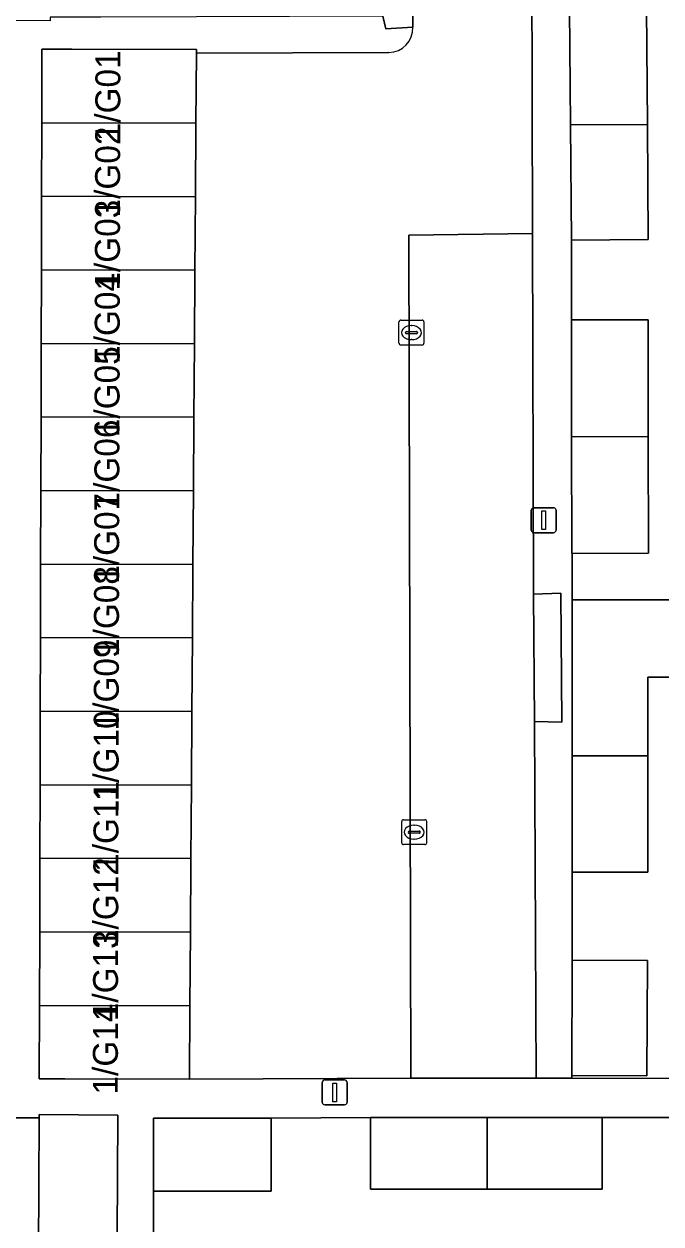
# Model space of a CAD drawing. Extents: x 160732 to 162107, y 387428 to 388479.
# Drawn here: x 161107.54 to 161133.07, y 387874.51 to 387922.63 of the extents above; entities that cross this region are included whole.
import ezdxf

# ---------------------------------------------------------------- set-up
doc = ezdxf.new("R2010")
doc.units = 0
for name, color, linetype in [('IMGEO_Erf', 7, 'Continuous'), ('IMGEO_Kolk', 7, 'Continuous'), ('IMGEO_Lichtmast', 7, 'Continuous'), ('IMGEO_Pand', 7, 'Continuous'), ('IMGEO_Pand_nummerreeks', 7, 'Continuous'), ('IMGEO_Parkeervlak_open', 7, 'Continuous'), ('IMGEO_Rijbaan_lokaal_open', 7, 'Continuous'), ('IMGEO_Voetpad_open', 7, 'Continuous')]:
    doc.layers.add(name, color=color, linetype=linetype)

msp = doc.modelspace()

# ---------------------------------------------------------------- linework, layer by layer
at = {"layer": 'IMGEO_Erf'}
for points in [[(161132.486, 387923.268), (161132.524, 387918.598), (161132.562, 387913.986), (161129.479, 387913.961), (161129.479, 387910.767), (161132.553, 387910.772), (161132.562, 387906.088), (161132.57, 387901.405), (161129.516, 387901.399), (161129.514, 387899.541), (161132.548, 387899.539), (161134.822, 387899.538)], [(161134.819, 387896.433), (161132.544, 387896.435), (161132.541, 387893.282), (161132.537, 387888.623), (161129.504, 387888.625), (161129.516, 387885.088), (161132.524, 387885.072), (161132.5, 387880.449), (161129.492, 387880.464), (161129.492, 387880.352), (161139.706, 387880.338)], [(161154.158, 387875.498), (161154.167, 387878.879), (161152.564, 387878.883), (161152.576, 387875.174), (161145.855, 387875.151), (161145.843, 387878.86), (161143.979, 387878.784), (161143.981, 387875.913), (161139.376, 387875.912), (161134.698, 387875.91), (161134.696, 387878.78), (161130.708, 387878.778), (161130.71, 387875.907), (161126.108, 387875.906), (161121.427, 387875.904), (161121.425, 387878.774), (161117.443, 387878.756), (161117.445, 387875.822), (161112.733, 387875.821), (161112.735, 387867.648)], [(161108.123, 387873.424), (161108.152, 387878.764), (161106.96, 387878.771)]]:
    msp.add_lwpolyline(points, dxfattribs=at)
at = {"layer": 'IMGEO_Kolk'}
for p, q in [((161122.57, 387909.83), (161122.57, 387910.682)), ((161122.645, 387910.756), (161123.497, 387910.756)), ((161123.571, 387910.682), (161123.571, 387909.83)), ((161122.829, 387910.25), (161122.829, 387910.262)), ((161123.267, 387910.213), (161122.869, 387910.213)), ((161122.872, 387910.299), (161123.27, 387910.299)), ((161123.058, 387910.536), (161123.083, 387910.536)), ((161123.313, 387910.262), (161123.313, 387910.25)), ((161123.497, 387909.756), (161122.645, 387909.756)), ((161123.081, 387909.976), (161123.056, 387909.976)), ((161122.678, 387889.796), (161122.678, 387890.648)), ((161122.753, 387890.722), (161123.605, 387890.722)), ((161123.166, 387890.502), (161123.191, 387890.502)), ((161123.679, 387890.648), (161123.679, 387889.796)), ((161122.937, 387890.216), (161122.937, 387890.228)), ((161123.375, 387890.179), (161122.977, 387890.179)), ((161122.98, 387890.265), (161123.378, 387890.265)), ((161123.189, 387889.942), (161123.164, 387889.942)), ((161123.421, 387890.228), (161123.421, 387890.216)), ((161123.605, 387889.722), (161122.753, 387889.722))]:
    msp.add_line(p, q, dxfattribs=at)
for points in [[(161122.57, 387909.83), (161122.57, 387910.682)], [(161122.645, 387910.756), (161123.497, 387910.756)], [(161123.571, 387910.682), (161123.571, 387909.83)], [(161123.497, 387909.756), (161122.645, 387909.756)], [(161122.678, 387889.796), (161122.678, 387890.648)], [(161122.753, 387890.722), (161123.605, 387890.722)], [(161123.679, 387890.648), (161123.679, 387889.796)], [(161123.605, 387889.722), (161122.753, 387889.722)]]:
    msp.add_lwpolyline(points, dxfattribs=at)
for centre, radius, start, end in [((161122.647, 387910.68), 0.0765, 91.552, 178.448), ((161122.647, 387910.68), 0.0765, 91.552, 178.448), ((161123.495, 387910.68), 0.0765, 1.552, 88.448), ((161123.495, 387910.68), 0.0765, 1.552, 88.448), ((161122.869, 387910.259), 0.0403, 85.8775, 175.7526), ((161122.866, 387910.249), 0.0366, 178.938, 274.7102), ((161123.27, 387910.256), 0.043, 264.8664, 352.4533), ((161123.274, 387910.261), 0.0386, 1.7309, 96.639), ((161122.647, 387909.832), 0.0765, 181.552, 268.448), ((161122.647, 387909.832), 0.0765, 181.552, 268.448), ((161123.495, 387909.832), 0.0765, 271.552, 358.448), ((161123.495, 387909.832), 0.0765, 271.552, 358.448), ((161122.755, 387890.646), 0.0765, 91.552, 178.448), ((161122.755, 387890.646), 0.0765, 91.552, 178.448), ((161123.603, 387890.646), 0.0765, 1.552, 88.448), ((161123.603, 387890.646), 0.0765, 1.552, 88.448), ((161122.977, 387890.225), 0.0403, 85.8775, 175.7526), ((161122.974, 387890.215), 0.0366, 178.938, 274.7102), ((161123.378, 387890.222), 0.043, 264.8664, 352.4533), ((161123.382, 387890.227), 0.0386, 1.7309, 96.639), ((161122.755, 387889.798), 0.0765, 181.552, 268.448), ((161122.755, 387889.798), 0.0765, 181.552, 268.448), ((161123.603, 387889.798), 0.0765, 271.552, 358.448), ((161123.603, 387889.798), 0.0765, 271.552, 358.448)]:
    msp.add_arc(centre, radius, start, end, dxfattribs=at)
for centre, major_axis, ratio, start_param, end_param in [((161123.057, 387910.256), (-0.387, 0.002), 0.722429, 4.712389, 7.853982), ((161123.082, 387910.256), (-0.39, 0.002), 0.717154, 1.570796, 4.712389), ((161123.165, 387890.222), (-0.387, 0.002), 0.722429, 4.712389, 7.853982), ((161123.19, 387890.222), (-0.39, 0.002), 0.717154, 1.570796, 4.712389)]:
    msp.add_ellipse(centre, major_axis=major_axis, ratio=ratio, start_param=start_param, end_param=end_param, dxfattribs=at)
at = {"layer": 'IMGEO_Lichtmast'}
for p, q in [((161127.873, 387902.331), (161127.873, 387903.131)), ((161127.873, 387903.131), (161127.873, 387902.331)), ((161127.973, 387903.231), (161128.763, 387903.231)), ((161128.763, 387903.231), (161127.973, 387903.231)), ((161128.863, 387903.131), (161128.863, 387902.331)), ((161128.863, 387902.331), (161128.863, 387903.131)), ((161128.763, 387902.231), (161127.973, 387902.231)), ((161127.973, 387902.231), (161128.763, 387902.231)), ((161119.597, 387880.287), (161120.387, 387880.287)), ((161120.387, 387880.287), (161119.597, 387880.287)), ((161119.497, 387879.387), (161119.497, 387880.187)), ((161119.497, 387880.187), (161119.497, 387879.387)), ((161120.487, 387880.187), (161120.487, 387879.387)), ((161120.487, 387879.387), (161120.487, 387880.187)), ((161120.387, 387879.287), (161119.597, 387879.287)), ((161119.597, 387879.287), (161120.387, 387879.287))]:
    msp.add_line(p, q, dxfattribs=at)
for points in [[(161128.293, 387903.106), (161128.443, 387903.106), (161128.443, 387902.356), (161128.293, 387902.356), (161128.293, 387903.106)], [(161119.917, 387880.162), (161120.067, 387880.162), (161120.067, 387879.412), (161119.917, 387879.412), (161119.917, 387880.162)]]:
    msp.add_lwpolyline(points, dxfattribs=at)
for centre, start, end in [((161127.973, 387903.131), 90, 180), ((161127.973, 387903.131), 90, 180), ((161128.763, 387903.131), 0, 90), ((161128.763, 387903.131), 360, 90), ((161127.973, 387902.331), 180, 270), ((161127.973, 387902.331), 180, 270), ((161128.763, 387902.331), 270, 0), ((161128.763, 387902.331), 270, 0), ((161119.597, 387880.187), 90, 180), ((161119.597, 387880.187), 90, 180), ((161120.387, 387880.187), 0, 90), ((161120.387, 387880.187), 360, 90), ((161119.597, 387879.387), 180, 270), ((161119.597, 387879.387), 180, 270), ((161120.387, 387879.387), 270, 0), ((161120.387, 387879.387), 270, 0)]:
    msp.add_arc(centre, 0.1, start, end, dxfattribs=at)
at = {"layer": 'IMGEO_Pand'}
for points in [[(161132.524, 387918.598), (161132.486, 387923.268), (161129.402, 387923.242), (161129.441, 387918.592)], [(161114.453, 387921.466), (161114.454, 387921.609), (161109.455, 387921.622), (161108.261, 387921.624), (161108.253, 387918.674), (161114.434, 387918.658)], [(161114.434, 387918.658), (161108.253, 387918.674), (161108.246, 387915.724), (161114.413, 387915.708)], [(161129.441, 387918.592), (161129.479, 387913.961), (161132.562, 387913.986), (161132.524, 387918.598)], [(161114.413, 387915.708), (161108.246, 387915.724), (161108.238, 387912.775), (161114.393, 387912.759)], [(161114.393, 387912.759), (161108.238, 387912.775), (161108.23, 387909.825), (161114.373, 387909.809)], [(161132.562, 387906.088), (161132.553, 387910.772), (161129.479, 387910.767), (161129.488, 387906.082)], [(161114.373, 387909.809), (161108.23, 387909.825), (161108.223, 387906.875), (161114.353, 387906.859)], [(161114.353, 387906.859), (161108.223, 387906.875), (161108.215, 387903.925), (161114.332, 387903.909)], [(161132.562, 387906.088), (161129.488, 387906.082), (161129.497, 387901.399), (161129.516, 387901.399), (161132.57, 387901.405)], [(161114.332, 387903.909), (161108.215, 387903.925), (161108.208, 387900.976), (161114.312, 387900.96)], [(161114.312, 387900.96), (161108.208, 387900.976), (161108.2, 387898.026), (161114.292, 387898.01)], [(161129.514, 387899.541), (161129.513, 387897.943), (161129.509, 387893.285), (161132.541, 387893.282), (161132.544, 387896.435), (161134.819, 387896.433), (161134.822, 387899.538), (161132.548, 387899.539)], [(161114.292, 387898.01), (161108.2, 387898.026), (161108.192, 387895.076), (161114.271, 387895.06)], [(161114.271, 387895.06), (161108.192, 387895.076), (161108.185, 387892.126), (161114.251, 387892.11)], [(161129.509, 387893.285), (161129.504, 387888.625), (161132.537, 387888.623), (161132.541, 387893.282)], [(161114.251, 387892.11), (161108.185, 387892.126), (161108.177, 387889.176), (161114.231, 387889.161)], [(161114.231, 387889.161), (161108.177, 387889.176), (161108.169, 387886.227), (161114.211, 387886.211)], [(161114.211, 387886.211), (161108.169, 387886.227), (161108.162, 387883.277), (161114.19, 387883.261)], [(161132.5, 387880.449), (161132.524, 387885.072), (161129.516, 387885.088), (161129.492, 387880.464)], [(161114.19, 387883.261), (161108.162, 387883.277), (161108.154, 387880.327), (161109.171, 387880.324), (161114.17, 387880.311)], [(161111.301, 387878.877), (161108.153, 387878.895), (161108.152, 387878.764), (161108.123, 387873.424), (161108.189, 387873.439), (161108.189, 387874.053), (161111.274, 387874.053)], [(161117.445, 387875.822), (161117.443, 387878.756), (161112.731, 387878.755), (161112.733, 387875.821)], [(161126.107, 387878.776), (161121.425, 387878.774), (161121.427, 387875.904), (161126.108, 387875.906)], [(161126.108, 387875.906), (161130.71, 387875.907), (161130.708, 387878.778), (161126.107, 387878.776)]]:
    msp.add_lwpolyline(points, close=True, dxfattribs=at)
at = {"layer": 'IMGEO_Parkeervlak_open'}
msp.add_lwpolyline([(161127.963, 387899.767), (161127.926, 387914.225), (161122.958, 387914.162), (161123.049, 387880.357), (161128.071, 387880.354), (161128.007, 387894.664)], close=True, dxfattribs=at)
at = {"layer": 'IMGEO_Rijbaan_lokaal_open'}
for points in [[(161122.958, 387914.162), (161127.926, 387914.225), (161127.885, 387930.449), (161127.846, 387935.311), (161127.866, 387945.068), (161123.097, 387945.063), (161123.102, 387943.562), (161123.156, 387927.578), (161123.128, 387922.5)], [(161122.168, 387921.485), (161114.453, 387921.466), (161114.434, 387918.658), (161114.413, 387915.708), (161114.393, 387912.759), (161114.373, 387909.809), (161114.353, 387906.859), (161114.332, 387903.909), (161114.312, 387900.96), (161114.292, 387898.01), (161114.271, 387895.06), (161114.251, 387892.11), (161114.231, 387889.161), (161114.211, 387886.211), (161114.19, 387883.261), (161114.17, 387880.311), (161123.049, 387880.357), (161122.958, 387914.162)]]:
    msp.add_lwpolyline(points, dxfattribs=at)
msp.add_arc((161122.14, 387922.473), 0.989, 271.6458, 1.5446, dxfattribs=at)
at = {"layer": 'IMGEO_Voetpad_open'}
for points in [[(161127.885, 387930.449), (161127.926, 387914.225), (161127.963, 387899.767), (161129.059, 387899.811), (161129.101, 387894.639), (161128.007, 387894.664), (161128.071, 387880.354), (161129.492, 387880.352), (161129.492, 387880.464), (161129.516, 387885.088), (161129.504, 387888.625), (161129.509, 387893.285), (161129.513, 387897.943), (161129.514, 387899.541), (161129.516, 387901.399), (161129.497, 387901.399), (161129.488, 387906.082), (161129.479, 387910.767), (161129.479, 387913.961), (161129.441, 387918.592), (161129.402, 387923.242)], [(161123.128, 387922.5), (161122.048, 387922.435), (161121.928, 387922.943), (161114.448, 387922.918), (161110.618, 387922.905), (161108.586, 387922.912), (161108.585, 387922.765), (161102.19, 387922.788)], [(161139.706, 387880.338), (161129.492, 387880.352), (161128.071, 387880.354), (161123.049, 387880.357), (161114.17, 387880.311), (161109.171, 387880.324), (161108.154, 387880.327), (161108.162, 387883.277), (161108.169, 387886.227), (161108.177, 387889.176), (161108.185, 387892.126), (161108.192, 387895.076), (161108.2, 387898.026), (161108.208, 387900.976), (161108.215, 387903.925), (161108.223, 387906.875), (161108.23, 387909.825), (161108.238, 387912.775), (161108.246, 387915.724), (161108.253, 387918.674), (161108.261, 387921.624), (161109.455, 387921.622), (161114.454, 387921.609), (161114.453, 387921.466), (161122.168, 387921.485)], [(161106.96, 387878.771), (161108.152, 387878.764), (161108.153, 387878.895), (161111.301, 387878.877), (161111.274, 387874.053)], [(161112.733, 387875.821), (161112.731, 387878.755), (161117.443, 387878.756), (161121.425, 387878.774), (161126.107, 387878.776), (161130.708, 387878.778), (161134.696, 387878.78)], [(161112.735, 387867.648), (161112.733, 387875.821)]]:
    msp.add_lwpolyline(points, dxfattribs=at)
for points in [[(161121.915, 387926.685), (161121.928, 387922.943), (161122.048, 387922.435), (161123.128, 387922.5), (161123.156, 387927.578), (161121.921, 387927.626)], [(161128.007, 387894.664), (161129.101, 387894.639), (161129.059, 387899.811), (161127.963, 387899.767)]]:
    msp.add_lwpolyline(points, close=True, dxfattribs=at)
msp.add_arc((161122.14, 387922.473), 0.989, 271.6458, 1.5446, dxfattribs=at)

# ---------------------------------------------------------------- texts
at = {"layer": 'IMGEO_Pand_nummerreeks'}
for s, p in [('1/G01', (161111.396, 387917.929)), ('1/G02', (161111.388, 387914.874)), ('1/G03', (161111.381, 387911.941)), ('1/G04', (161111.373, 387909.002)), ('1/G05', (161111.366, 387906.063)), ('1/G06', (161111.358, 387903.124)), ('1/G07', (161111.351, 387900.185)), ('1/G08', (161111.343, 387897.249)), ('1/G09', (161111.336, 387894.304)), ('1/G10', (161111.329, 387891.463)), ('1/G11', (161111.322, 387888.631)), ('1/G12', (161111.314, 387885.575)), ('1/G13', (161111.306, 387882.642)), ('1/G14', (161111.299, 387879.703))]:
    msp.add_text(s, height=1, rotation=89.8549, dxfattribs=at).set_placement(p)

doc.saveas('drawing.dxf')
